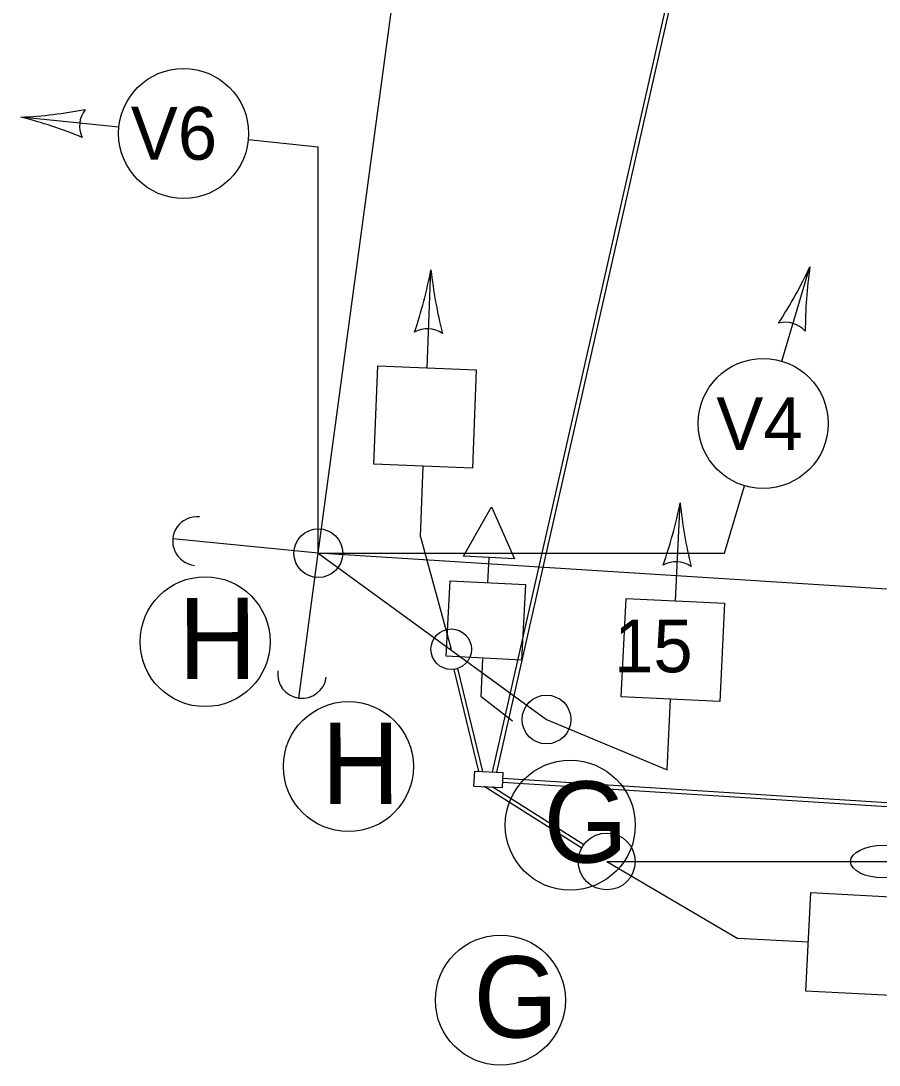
# Model space of a CAD drawing. Extents: x 647787 to 668496, y 640478 to 654412.
# Drawn here: x 659805.3 to 659858.1, y 647363.5 to 647427.8 of the extents above; entities that cross this region are included whole.
import ezdxf

# ---------------------------------------------------------------- set-up
doc = ezdxf.new("R2010")
doc.units = 0
for name, color, linetype in [('TEMP_SIGNAL_HEAD_STAGE 1A', 7, 'Continuous'), ('TEMP_SIGNAL_HEAD_STAGE 2', 7, 'Continuous'), ('TEMP_SIGNAL_HEAD_STAGE 2 SALEM', 7, 'Continuous'), ('TEMP_SIGNAL_HEAD_Stage 3', 7, 'Continuous'), ('TEMP_SIGNAL_POLES_STAGE 1A', 7, 'Continuous'), ('TEMP_SIGNAL_POLES_STAGE 2', 7, 'Continuous'), ('TEMP_SIGNAL_POLES_STAGE 3', 7, 'Continuous'), ('TEMP_SIGNAL_POLES_STAGE 5', 7, 'Continuous'), ('TEXT_TEMP_SIGNAL_POLES_STAGE 2', 7, 'Continuous'), ('TEXT_TEMP_SIGNAL_POLES_STAGE 3', 7, 'Continuous'), ('TEXT_TEMP_SIGNAL_POLES_STAGE 4', 7, 'Continuous'), ('TEXT_TEMP_SIGNAL_POLES_STAGE 5', 7, 'Continuous')]:
    doc.layers.add(name, color=color, linetype=linetype)

msp = doc.modelspace()

# ---------------------------------------------------------------- linework, layer by layer
at = {"layer": 'TEMP_SIGNAL_HEAD_STAGE 1A'}
for p, q in [((659857.619, 647484.469), (659834.309, 647381.543)), ((659857.619, 647484.469), (659834.309, 647381.543)), ((659857.619, 647484.469), (659834.309, 647381.543)), ((659857.876, 647484.469), (659834.562, 647381.53)), ((659857.876, 647484.469), (659834.562, 647381.53)), ((659857.876, 647484.469), (659834.562, 647381.53)), ((659833.476, 647381.586), (659831.959, 647387.865)), ((659833.476, 647381.586), (659831.959, 647387.865)), ((659833.476, 647381.586), (659831.959, 647387.865)), ((659833.736, 647381.572), (659832.202, 647387.923)), ((659833.736, 647381.572), (659832.202, 647387.923)), ((659833.736, 647381.572), (659832.202, 647387.923)), ((659833.185, 647380.682), (659833.232, 647381.598)), ((659833.185, 647380.682), (659833.232, 647381.598)), ((659833.185, 647380.682), (659833.232, 647381.598)), ((659833.232, 647381.598), (659834.98, 647381.509)), ((659833.232, 647381.598), (659834.98, 647381.509)), ((659833.232, 647381.598), (659834.98, 647381.509)), ((659834.933, 647380.594), (659834.98, 647381.509)), ((659834.933, 647380.594), (659834.98, 647381.509)), ((659834.933, 647380.594), (659834.98, 647381.509)), ((659833.185, 647380.683), (659834.933, 647380.594)), ((659833.185, 647380.683), (659834.933, 647380.594)), ((659833.185, 647380.683), (659834.933, 647380.594)), ((659839.814, 647376.864), (659833.804, 647380.651)), ((659839.814, 647376.864), (659833.804, 647380.651)), ((659839.814, 647376.864), (659833.804, 647380.651)), ((659839.947, 647377.075), (659834.314, 647380.625)), ((659839.947, 647377.075), (659834.314, 647380.625)), ((659839.947, 647377.075), (659834.314, 647380.625)), ((659834.949, 647380.916), (659955.369, 647373.287)), ((659834.949, 647380.916), (659955.369, 647373.287)), ((659834.949, 647380.916), (659955.369, 647373.287)), ((659834.962, 647381.165), (659955.606, 647373.523)), ((659834.962, 647381.165), (659955.606, 647373.523)), ((659834.962, 647381.165), (659955.606, 647373.523))]:
    msp.add_line(p, q, dxfattribs=at)
at = {"layer": 'TEMP_SIGNAL_HEAD_STAGE 2'}
for p, q in [((659811.338, 647421.249), (659805.304, 647421.855)), ((659823.607, 647420.017), (659819.298, 647420.45)), ((659823.607, 647395.017), (659823.607, 647420.017)), ((659852.127, 647406.834), (659853.858, 647412.647)), ((659848.607, 647395.017), (659849.843, 647399.167)), ((659845.579, 647392.083), (659845.876, 647398.116)), ((659823.607, 647395.017), (659837.647, 647384.78)), ((659823.607, 647395.017), (659848.607, 647395.017)), ((659845.068, 647381.686), (659845.281, 647386.028)), ((659837.647, 647384.78), (659845.068, 647381.686))]:
    msp.add_line(p, q, dxfattribs=at)
msp.add_lwpolyline([(659848.31, 647385.879), (659842.253, 647386.176), (659842.551, 647392.232), (659848.608, 647391.934)], close=True, dxfattribs=at)
for centre in [(659815.318, 647420.849), (659850.985, 647403.001)]:
    msp.add_circle(centre, 4, dxfattribs=at)
for centre, radius, start, end in [((659803.82, 647451.289), 29.472, 272.88617, 280.62428), ((659810.544, 647421.329), 1.629, 142.41952, 206.11415), ((659798.009, 647393.302), 29.47, 67.93049, 75.6686), ((659827.19, 647425.187), 29.47, 327.07659, 334.81471), ((659883.046, 647408.561), 29.472, 172.03227, 179.77039), ((659852.355, 647407.599), 1.629, 41.56563, 105.26026), ((659816.988, 647403.954), 29.472, 340.83871, 348.57683), ((659875.198, 647401.092), 29.472, 185.79346, 193.53157), ((659845.618, 647392.856), 1.629, 55.33783, 119.03246)]:
    msp.add_arc(centre, radius, start, end, dxfattribs=at)
at = {"layer": 'TEMP_SIGNAL_HEAD_STAGE 2 SALEM'}
for points in [[(659834.271, 647397.862), (659835.676, 647394.665), (659832.547, 647394.824)], [(659834.271, 647397.862), (659835.676, 647394.665), (659832.547, 647394.824)], [(659836.115, 647388.441), (659831.477, 647388.678), (659831.713, 647393.317), (659836.352, 647393.08)], [(659836.115, 647388.441), (659831.477, 647388.678), (659831.713, 647393.317), (659836.352, 647393.08)]]:
    msp.add_lwpolyline(points, close=True, dxfattribs=at)
for points in [[(659834.033, 647393.198), (659834.111, 647394.745)], [(659834.033, 647393.198), (659834.111, 647394.745)], [(659833.62, 647386.177), (659833.74, 647388.518)], [(659833.62, 647386.177), (659833.74, 647388.518)], [(659835.549, 647384.675), (659833.62, 647386.177)], [(659835.549, 647384.675), (659833.62, 647386.177)]]:
    msp.add_lwpolyline(points, dxfattribs=at)
at = {"layer": 'TEMP_SIGNAL_HEAD_Stage 3'}
for p, q in [((659811.338, 647421.249), (659805.304, 647421.855)), ((659823.607, 647420.017), (659819.298, 647420.45)), ((659823.607, 647395.017), (659823.607, 647420.017)), ((659852.127, 647406.834), (659853.858, 647412.647)), ((659848.607, 647395.017), (659849.843, 647399.167)), ((659823.607, 647395.017), (659848.607, 647395.017))]:
    msp.add_line(p, q, dxfattribs=at)
for centre in [(659815.318, 647420.849), (659850.985, 647403.001)]:
    msp.add_circle(centre, 4, dxfattribs=at)
for centre, radius, start, end in [((659803.82, 647451.289), 29.472, 272.88617, 280.62428), ((659810.544, 647421.329), 1.629, 142.41952, 206.11415), ((659798.009, 647393.302), 29.47, 67.93049, 75.6686), ((659827.19, 647425.187), 29.47, 327.07659, 334.81471), ((659883.046, 647408.561), 29.472, 172.03227, 179.77039), ((659852.355, 647407.599), 1.629, 41.56563, 105.26026)]:
    msp.add_arc(centre, radius, start, end, dxfattribs=at)
at = {"layer": 'TEMP_SIGNAL_POLES_STAGE 1A'}
for p, q in [((659830.299, 647406.425), (659830.538, 647412.461)), ((659829.889, 647396.023), (659830.06, 647400.367)), ((659829.889, 647396.023), (659831.789, 647389.103)), ((659841.36, 647376.037), (659901.36, 647376.037)), ((659841.36, 647376.037), (659849.416, 647371.31)), ((659841.36, 647376.037), (659856.36, 647376.037)), ((659849.415, 647371.313), (659853.757, 647371.093))]:
    msp.add_line(p, q, dxfattribs=at)
for points in [[(659833.09, 647400.247), (659827.03, 647400.486), (659827.269, 647406.545), (659833.329, 647406.305)], [(659853.603, 647368.064), (659853.91, 647374.121), (659859.966, 647373.813), (659859.658, 647367.757)]]:
    msp.add_lwpolyline(points, close=True, dxfattribs=at)
for centre, radius in [((659831.789, 647389.103), 1.25), ((659841.358, 647376.041), 1.75)]:
    msp.add_circle(centre, radius, dxfattribs=at)
for centre, radius, start, end in [((659801.595, 647418.018), 29.472, 341.39378, 349.1319), ((659859.83, 647415.72), 29.472, 186.34853, 194.08664), ((659830.331, 647407.198), 1.629, 55.8929, 119.58753)]:
    msp.add_arc(centre, radius, start, end, dxfattribs=at)
msp.add_ellipse((659858.36, 647376.037), major_axis=(2, 0), ratio=0.5, dxfattribs=at)
at = {"layer": 'TEMP_SIGNAL_POLES_STAGE 2'}
for p, q in [((659823.607, 647395.017), (659836.648, 647491.699)), ((659823.607, 647395.017), (659814.651, 647395.908)), ((659822.404, 647386.098), (659823.607, 647395.017)), ((659962.344, 647386.22), (659823.607, 647395.017))]:
    msp.add_line(p, q, dxfattribs=at)
for centre in [(659823.607, 647395.017), (659837.647, 647384.78)]:
    msp.add_circle(centre, 1.5, dxfattribs=at)
for centre, start, end in [((659816.144, 647395.759), 84.31911, 264.31911), ((659822.604, 647387.584), 172.31754, 352.31754)]:
    msp.add_arc(centre, 1.5, start, end, dxfattribs=at)
at = {"layer": 'TEMP_SIGNAL_POLES_STAGE 3'}
for p, q in [((659823.607, 647395.017), (659836.648, 647491.699)), ((659823.607, 647395.017), (659814.651, 647395.908)), ((659822.404, 647386.098), (659823.607, 647395.017)), ((659967.334, 647385.904), (659823.607, 647395.017))]:
    msp.add_line(p, q, dxfattribs=at)
msp.add_circle((659823.607, 647395.017), 1.5, dxfattribs=at)
for centre, start, end in [((659816.144, 647395.759), 84.31911, 264.31911), ((659822.604, 647387.584), 172.31754, 352.31754)]:
    msp.add_arc(centre, 1.5, start, end, dxfattribs=at)
at = {"layer": 'TEMP_SIGNAL_POLES_STAGE 5'}
for q in [(659901.36, 647376.037), (659901.36, 647376.037), (659856.36, 647376.037), (659856.36, 647376.037)]:
    msp.add_line((659841.36, 647376.037), q, dxfattribs=at)
for centre, radius in [((659831.789, 647389.103), 1.25), ((659831.789, 647389.103), 1.25), ((659841.358, 647376.041), 1.75), ((659841.358, 647376.041), 1.75)]:
    msp.add_circle(centre, radius, dxfattribs=at)
msp.add_ellipse((659858.36, 647376.037), major_axis=(2, 0), ratio=0.5, dxfattribs=at)
msp.add_ellipse((659858.36, 647376.037), major_axis=(2, 0), ratio=0.5, dxfattribs=at)
at = {"layer": 'TEXT_TEMP_SIGNAL_POLES_STAGE 2'}
for centre in [(659816.642, 647389.57), (659839.112, 647378.275)]:
    msp.add_circle(centre, 4, dxfattribs=at)
at = {"layer": 'TEXT_TEMP_SIGNAL_POLES_STAGE 3'}
msp.add_circle((659816.642, 647389.57), 4, dxfattribs=at)
at = {"layer": 'TEXT_TEMP_SIGNAL_POLES_STAGE 4'}
for centre in [(659825.456, 647381.882), (659834.811, 647367.506)]:
    msp.add_circle(centre, 4, dxfattribs=at)
at = {"layer": 'TEXT_TEMP_SIGNAL_POLES_STAGE 5'}
for centre in [(659825.456, 647381.882), (659834.811, 647367.506)]:
    msp.add_circle(centre, 4, dxfattribs=at)

# ---------------------------------------------------------------- texts
at = {"layer": 'TEXT_TEMP_SIGNAL_POLES_STAGE 2'}
for s, height, rotation, p in [('V6', 3.25, 359.93402, (659812.062, 647419.242)), ('V4', 3.25, 359.93402, (659848.094, 647401.368)), ('H', 5, 0.10961, (659814.994, 647387.264)), ('G', 5, 0.10961, (659837.464, 647375.968))]:
    msp.add_text(s, height=height, rotation=rotation, dxfattribs=at).set_placement(p)
msp.add_text('15', height=3.25, dxfattribs=at).set_placement((659841.808, 647387.685))
at = {"layer": 'TEXT_TEMP_SIGNAL_POLES_STAGE 3'}
for s, height, rotation, p in [('V6', 3.25, 359.93402, (659812.062, 647419.242)), ('V4', 3.25, 359.93402, (659848.094, 647401.368)), ('H', 5, 0.10961, (659814.994, 647387.264))]:
    msp.add_text(s, height=height, rotation=rotation, dxfattribs=at).set_placement(p)
at = {"layer": 'TEXT_TEMP_SIGNAL_POLES_STAGE 4'}
for s, p in [('H', (659823.808, 647379.575)), ('G', (659833.163, 647365.2))]:
    msp.add_text(s, height=5, rotation=0.10961, dxfattribs=at).set_placement(p)
at = {"layer": 'TEXT_TEMP_SIGNAL_POLES_STAGE 5'}
for s, p in [('H', (659823.808, 647379.575)), ('G', (659833.163, 647365.2))]:
    msp.add_text(s, height=5, rotation=0.10961, dxfattribs=at).set_placement(p)

doc.saveas('drawing.dxf')
